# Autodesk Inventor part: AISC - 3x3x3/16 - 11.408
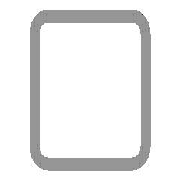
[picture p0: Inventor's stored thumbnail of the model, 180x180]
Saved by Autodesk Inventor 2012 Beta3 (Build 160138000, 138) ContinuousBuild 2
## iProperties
IsCustomPart: 1
Created: 2010-11
Part Number: AISC - 3x3x3/16 - 11.408
Material: Steel, Mild
Description: Tube
Document SubType Name: Modeling
Standard: ANSI
Designer: Beta-8540w
Standards Organization: ANSI
Language: en-US
Size Designation: 3x3x3/16
Categories: <MemberInstance><Categories><Category DisplayName="Structural Shapes" InternalName="089c4875-fa83-4c05-b084-43b9cc11f5ed" Mnemonic="GRDR"><CategoryParameter Dis
Stock Number: 3x3x3/16
Density: 7.86 g/cm^3
G_L: 11.408 in
G_W: 3.000 in
G_H: 3.000 in
+F48483C9-E9F5-4C3B-A2E0-95EBE26CBBEF+CUTDETAIL1: Miter 45.00 deg
_CCFamilyMember: 9
_CCFamilyDisplayName: ANSI AISC (Square) - Tube
_FrameMemberDoc: Frame Member File
_Version: 15.0.0
_GetPNFromCC: 1
Author: Beta-8540w
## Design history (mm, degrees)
node "Start plane"
node "End plane"
sketch "Sketch"
  geometry: L1 (-38.1, -28.575)-(-38.1, 28.575); L2 (-28.575, 38.1)-(28.575, 38.1); L3 (38.1, 28.575)-(38.1, -28.575); L4 (28.575, -38.1)-(-28.575, -38.1); L5 (-28.575, 33.337)-(28.575, 33.338); L6 (33.338, 28.575)-(33.338, -28.575); L7 (28.575, -33.337)-(-28.575, -33.338); L8 (-33.338, -28.575)-(-33.338, 28.575); L9 (0, 56.102)-(0, -56.102) reference; L10 (-56.102, 0)-(56.102, 0) reference; A1 r 9.525 centre (-28.575, -28.575) between (-38.1, -28.575) and (-28.575, -38.1); A2 r 9.525 centre (-28.575, 28.575) between (-28.575, 38.1) and (-38.1, 28.575); A3 r 9.525 centre (28.575, 28.575) between (38.1, 28.575) and (28.575, 38.1); A4 r 9.525 centre (28.575, -28.575) between (28.575, -38.1) and (38.1, -28.575); A5 r 4.763 centre (-28.575, 28.575) between (-28.575, 33.337) and (-33.338, 28.575); A6 r 4.763 centre (28.575, 28.575) between (33.338, 28.575) and (28.575, 33.338); A7 r 4.763 centre (28.575, -28.575) between (28.575, -33.337) and (33.338, -28.575); A8 r 4.763 centre (-28.575, -28.575) between (-33.338, -28.575) and (-28.575, -33.338)
  constraints: 16 end point, 16 point on circle, 8 centre point, 8 tangent, 4 parallel, 3 equal radius, 2 perpendicular, 7 other
  dimensions: "d10" = 76.2 distance between parallel lines of L2 L4 (= G_H); "d11" = 76.2 distance between parallel lines of L1 L3 (= G_W); "d12" = 4.7625 distance between parallel lines of L3 L6 (= G_T); "d15" = 38.1 distance between parallel lines of L2 L10 (= 0.5 x d10); "d16" = 38.1 distance between parallel lines of L9 L3 (= 0.5 x d11); "d17" = 9.525 radius of A1 (= G_IR)
extrude "Body" new body sketch "Sketch" stored distance "d3" = 289.76513 (= G_L); taper "d4" = 0 deg
node "Driven Length"
  sketch "Sketch3"
    geometry: L1 (0, 0)-(10, 0) reference
    constraints: 2 end point, 1 horizontal
  workplane "Work Plane3"
  sketch "Sketch4"
    geometry: L1 (-2, 0)-(12, 0) reference; L2 (-2, 289.765)-(12, 289.765) reference
    dimensions: "d19" = 289.76513 distance between parallel lines of L1 L2 (derived)
workplane "Work Plane4"
split "Split1"
body "Solid1"
other parameters: "G_W" = 76.2 [user parameter; used in 1 equation term], "G_H" = 76.2 [user parameter; used in 1 equation term], "G_T" = 4.7625 [user parameter; used in 1 equation term], "G_IR" = 9.525 [user parameter; used in 1 equation term], "G_L" = 289.76513 (= d19) [user parameter; used in 1 equation term], "G_OFFSET_START" = 0 [user parameter; used in 1 equation term], "G_OFFSET_END" = 35.76513 [user parameter; used in 1 equation term], "d13" = 0 (computed from G_OFFSET_START), "d14" = 289.76513 (= G_OFFSET_END + B_L), "B_L" = 254 [user parameter; used in 1 equation term], "d18" = 90 deg
